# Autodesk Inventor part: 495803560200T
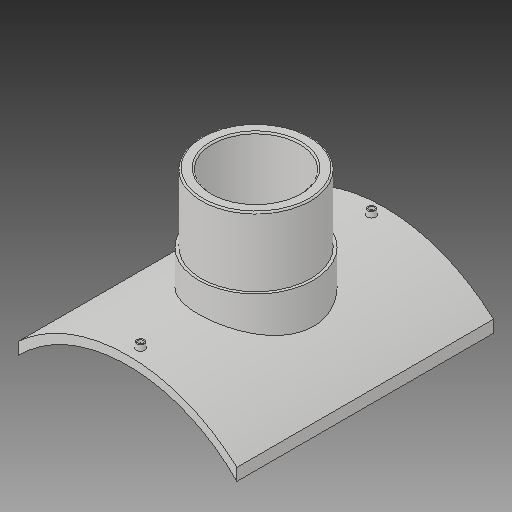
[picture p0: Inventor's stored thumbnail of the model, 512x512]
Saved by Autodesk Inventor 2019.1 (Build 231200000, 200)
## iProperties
Created: 2017-10
Part Number: 495803560200T
Material: Generic
Description: PLASSON BRANCH SADDLE  560x200
Document SubType Name: Modeling
Designer: KIM
Mass: 2754.05 g
Surface Area: 3037.44 cm^2
Volume: 2754.05 cm^3
Density: 1 g/cm^3
Appearance: Default
Author: KIM
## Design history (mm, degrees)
derived "495803.ipt"
feature "Solid1::495803.ipt"
tag "TaggingFeature1"
body "Solid1"
other parameters: "d1" = 16, "d4" = 0, "d12" = 305.6, "d13" = 14, "d14" = 211.5, "d16" = 5 deg, "d18" = 4, "d19" = 14, "d20" = 0, "d21" = 3, "d22" = 0, "d23" = 476, "d25" = 16, "d28" = 0, "d29" = 9.6, "d31" = 0, "d33" = 0, "d34" = 5.6, "d37" = 126, "d38" = 0, "d39" = 2.8, "x_" = 16, "D_" = 16
